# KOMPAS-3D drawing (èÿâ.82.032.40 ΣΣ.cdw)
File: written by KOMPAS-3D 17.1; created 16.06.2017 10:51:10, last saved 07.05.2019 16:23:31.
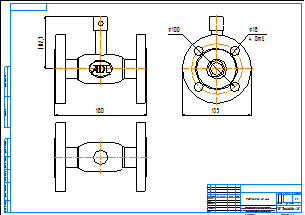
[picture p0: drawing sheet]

Sheet 1: A2, landscape

Title block, sheet 1: name: КШГ.82.032.40 фф; material: Внимание! Данный продукт является объектом авторского права ООО «Торговый Дом АДЛ». / Запрещается изменение, копирование, распространение / (в том числе путем копирования на другие сайты и ресурсы в Интернете) / или любое иное использование информации и объектов без предварительного / согласия правообладателя (ООО «Торговый Дом АДЛ»).; scale: 1:1; sheets: 1; organisation: ООО "Торговый дом АДЛ"; sheet format: A2; stored path: C:\Users\tra\Desktop\2д чертежи\Шаровые краны БИВАЛ\КШ_Бивал_серия_82_85\KOMPAS 2D\КШГ.82.032.40 фф.cdw

Views: Спереди 1, Проекционный вид 2, Проекционный вид 3
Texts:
  Klimkovich
  ADL
Dimensions and other numbers on the sheet: 180; 102,7; 100; 18; 4 Отв.; 135; 1:1; 1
